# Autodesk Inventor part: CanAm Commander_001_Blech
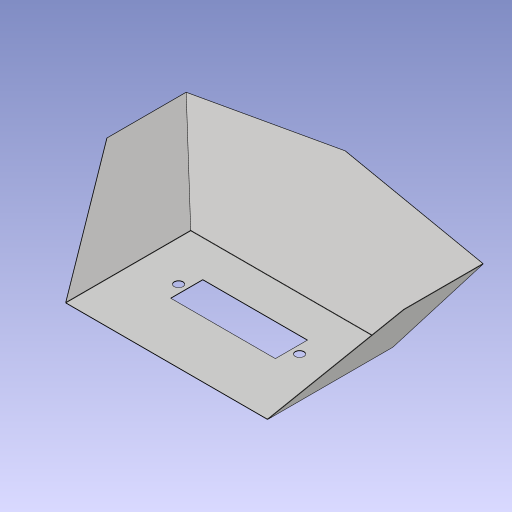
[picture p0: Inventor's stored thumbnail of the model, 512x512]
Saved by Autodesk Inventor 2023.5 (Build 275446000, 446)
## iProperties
Part Number: CanAm Commander_001_Blech
Material: Generisch
Document SubType Name: Blech
Designer: wondraschek
Density: 1 g/cm^3
Sheet Metal Rule: Standard_mm
Appearance: Vorgabe
Flat Pattern Width: 28.7833 cm
Flat Pattern Length: 46.96 cm
Flat Pattern Area: 1351.66 cm^2
Sheet Metal Width: 287,833 mm
Sheet Metal Length: 469,600 mm
Sheet Metal Area: 135166,289 mm^2
Author: wondraschek
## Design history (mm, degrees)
derived "CanAm Commander_SKI.ipt"
  sketch "Skizze3_1"
    geometry: L1 (0, 775.799)-(0, -205.388) reference; L2 (0, 315.971)-(183.976, 315.971) reference; L3 (183.976, 315.971)-(183.976, 356.128) reference; L4 (183.976, 356.128)-(215.226, 386.642) reference; L5 (215.226, 386.642)-(564.015, 470.928) reference; L6 (564.015, 470.928)-(491.478, 359.217) reference; L7 (0, -65.218)-(150, -65.218) reference; L8 (150, -65.218)-(275, 59.782) reference; L9 (0, 315.971)-(0, -65.218) reference; L10 (275, 59.782)-(275, 177.57) reference; L11 (275, 177.57)-(491.478, 359.217) reference; L12 (-65, 169.782)-(65, 169.782) reference; L13 (65, 169.782)-(65, 129.782) reference; L14 (65, 129.782)-(-65, 129.782) reference; L15 (-65, 129.782)-(-65, 169.782) reference; L16 (-75, 149.782)-(75, 149.782) reference; L17 (-87.5, 114.782)-(87.5, 114.782) reference; L18 (87.5, 114.782)-(87.5, 184.782) reference; L19 (87.5, 184.782)-(-87.5, 184.782) reference; L20 (-87.5, 184.782)-(-87.5, 114.782) reference; L21 (-87.5, 114.782)-(87.5, 184.782) reference; L22 (87.5, 114.782)-(-87.5, 184.782) reference; C1 r 5.5 at (-75, 149.782) reference; C2 r 5.5 at (75, 149.782) reference; 5 further points
node "Fläche1"
  sketch "Skizze1"
    geometry: L1 (0, 0)-(0, -154.866) reference; L2 (0, 0)-(250, 0) reference; L3 (250, 0)-(250, -154.866) reference; L4 (250, -154.866)-(0, -154.866) reference; 1 further point
node "Fläche3"
  sketch "Skizze3"
    geometry: L1 (125, 132.791)-(-58.976, 106.707) reference; L2 (125, 132.791)-(308.976, 106.707) reference; L3 (308.976, 106.707)-(250, 0) reference; L4 (0, 0)-(250, 0) reference; L5 (-58.976, 106.707)-(0, 0) reference; 1 further point
node "Fläche2"
  sketch "Skizze2"
    geometry: L1 (-109.626, 208.219)-(0, 154.866) reference; L2 (-109.626, 110.131)-(-109.626, 208.219) reference; L3 (-109.626, 110.131)-(0, 0) reference; L4 (0, 154.866)-(0, 0) reference; 1 further point
mirror "Spiegeln2"
feature "Biegung3" dims "d1" = 0.5 (= Stärke), "d17" = 0.5 (= BreiteBiegungsfreistellung), "d18" = 0.25 (= TiefeBiegungsfreistellung), "d19" = 1 (= MinimalRest), "d20" = 0.5 (= Übergangsradius), "d21" = 0.5 (= Biegeradius), "AbstandVerbindung" = 0.01
  node "Volumenkörper2"
feature "Biegung4" dims "d16" = 0.5 (= Stärke), "d22" = 0.5 (= BreiteBiegungsfreistellung), "d23" = 0.25 (= TiefeBiegungsfreistellung), "d24" = 1 (= MinimalRest), "d25" = 0.5 (= Übergangsradius), "d26" = 0.5 (= Biegeradius), "AbstandVerbindung" = 0.01
  node "Volumenkörper1"
feature "Ausschneiden1" dims "d27" = 0.5 (= Stärke), "d28" = 0
tag "Bezeichnung1"
feature "Grobblech1" dims "d1" = 0.5 (= Stärke)
feature "Grobblech2" dims "d16" = 0.5 (= Stärke)
feature "Grobblech3" dims "d1" = 0.5 (= Stärke), "d7" = 0.5 (= Biegeradius), "d8" = 0.5 (= BreiteBiegungsfreistellung), "d10" = 1 (= MinimalRest)
feature "Biegung2" dims "d1" = 0.5 (= Stärke), "d7" = 0.5 (= Biegeradius), "d8" = 0.5 (= BreiteBiegungsfreistellung), "d9" = 0.25 (= TiefeBiegungsfreistellung), "d10" = 1 (= MinimalRest), "d11" = 0.5 (= Übergangsradius), "AbstandVerbindung" = 0.01
feature "Anordnung von Volumenkörper2:1"
node "Volumenkörper3"
feature "Volumenkörper1::CanAm Commander_SKI.ipt"
node "Flä1"
feature "Definition1"
other parameters: "Stärke" = 0.5 (derived), "KFaktor" = 4.4, "Biegeradius" = 0.5 (= Stärke), "BreiteBiegungsfreistellung" = 0.5 (= Stärke), "TiefeBiegungsfreistellung" = 0.25 (= 0.5 x Stärke), "GrößeEckenfreistellung" = 2 (= 4 x Stärke), "MinimalRest" = 1 (= 2 x Stärke), "Übergangsradius" = 0.5 (= Biegeradius), "JacobiRadiusGröße" = 0.5 (= Biegeradius), "Abstandsgröße" = 0.5 (= Stärke), "Abstandsgröße" = 0.5, "Biegeradius" = 0.5, "BreiteBiegungsfreistellung" = 0.5, "GrößeEckenfreistellung" = 2, "JacobiRadiusGröße" = 0.5, "MinimalRest" = 1, "Stärke" = 0.5, "TiefeBiegungsfreistellung" = 0.25, "Übergangsradius" = 0.5
